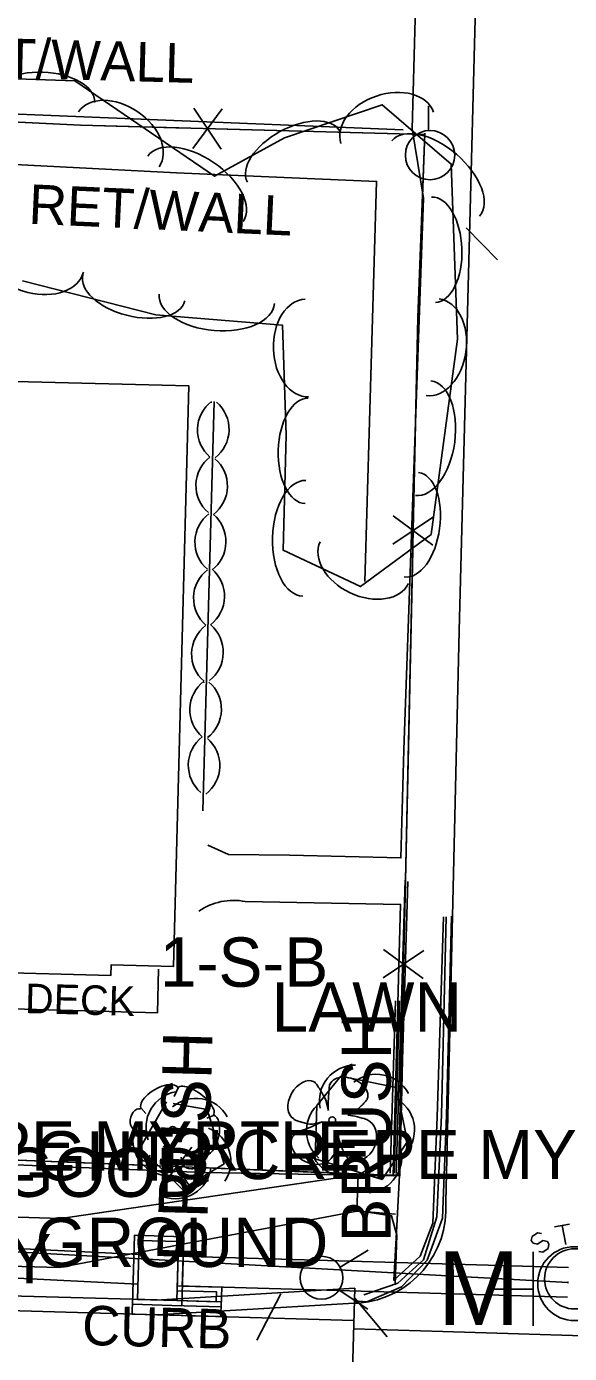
# Model space of a CAD drawing. Extents: x 978516 to 993312, y 1836504 to 1846212.
# Drawn here: x 992666.6 to 992721.7, y 1842882.7 to 1843017.4 of the extents above; entities that cross this region are included whole.
import ezdxf

# ---------------------------------------------------------------- set-up
doc = ezdxf.new("R2010")
doc.units = 0
for name, color, linetype in [('R_Drainage', 7, 'Continuous'), ('R_Proposed Road', 7, 'Continuous'), ('S_BUILDING', 7, 'Continuous'), ('S_CURB', 7, 'Continuous'), ('S_CURB_ANNOT', 7, 'Continuous'), ('S_EDGE_PAVEMENT', 7, 'Continuous'), ('S_FENCE', 7, 'Continuous'), ('S_FENCE_ANNOT', 7, 'Continuous'), ('S_IRON_PIN_ANNOT', 7, 'Continuous'), ('S_LANDSCAPING', 7, 'Continuous'), ('S_MANHOLE', 7, 'Continuous'), ('S_MISC_STRUCTURES', 7, 'Continuous'), ('S_MISC_STRUCTURES_ANNOT', 7, 'Continuous'), ('S_SIDEWALK', 7, 'Continuous'), ('S_STORM_SEWER', 7, 'Continuous'), ('S_STORM_SEWER_ANNOT', 7, 'Continuous'), ('S_SURVEY_TEXT_ANNOT', 7, 'Continuous'), ('S_TREE', 7, 'Continuous'), ('S_TREE_ANNOT', 7, 'Continuous'), ('S_UTILITY_POLE', 7, 'Continuous'), ('S_UTL_PT_SYM', 7, 'Continuous'), ('S_WALL', 7, 'Continuous'), ('S_WATER_UTILITIES', 7, 'Continuous')]:
    doc.layers.add(name, color=color, linetype=linetype)

msp = doc.modelspace()

# ---------------------------------------------------------------- linework, layer by layer
at = {"layer": 'R_Drainage'}
for p, q in [((992677.99, 1842892.77), (992612.06, 1842896.1)), ((992677.9, 1842889.77), (992611.98, 1842893.1)), ((992721.57, 1842891.46), (992681.98, 1842892.61)), ((992721.48, 1842888.46), (992681.9, 1842889.61))]:
    msp.add_line(p, q, dxfattribs=at)
for points in [[(992682.4, 1842889.59), (992682.54, 1842894.59), (992677.54, 1842894.73), (992677.34, 1842887.74), (992682.34, 1842887.59)], [(992681.88, 1842889.11), (992682.03, 1842894.11), (992678.03, 1842894.22), (992677.86, 1842888.22), (992681.85, 1842888.11)], [(992681.34, 1842887.62), (992686.34, 1842887.48), (992686.4, 1842889.48), (992682.4, 1842889.59)], [(992681.85, 1842888.11), (992685.85, 1842887.99), (992685.88, 1842888.99), (992681.88, 1842889.11)]]:
    msp.add_lwpolyline(points, dxfattribs=at)
for points in [[(992682.54, 1842894.59), (992677.54, 1842894.73), (992677.34, 1842887.74), (992682.34, 1842887.59)], [(992682.54, 1842894.59), (992677.54, 1842894.73), (992677.34, 1842887.74), (992682.34, 1842887.59)], [(992682.03, 1842894.11), (992678.03, 1842894.22), (992677.86, 1842888.22), (992681.85, 1842888.11)], [(992682.03, 1842894.11), (992678.03, 1842894.22), (992677.86, 1842888.22), (992681.85, 1842888.11)], [(992686.35, 1842887.98), (992677.36, 1842888.24), (992677.31, 1842886.74), (992686.31, 1842886.48)]]:
    msp.add_lwpolyline(points, close=True, dxfattribs=at)
at = {"layer": 'R_Proposed Road'}
for p, q in [((992700.23, 1842900.88), (992670.09, 1842896.45)), ((992700.12, 1842897.19), (992700.23, 1842900.88)), ((992528.4, 1842900.48), (992670.09, 1842896.45)), ((992669.94, 1842891.45), (992700.12, 1842897.19)), ((992528.26, 1842895.48), (992669.94, 1842891.45)), ((992528.17, 1842892.48), (992679.86, 1842888.17)), ((992528.13, 1842890.98), (992699.8, 1842886.1)), ((992679.72, 1842888.16), (992699.9, 1842889.37)), ((992698.6, 1842843.61), (992699.9, 1842889.37)), ((992679.81, 1842886.67), (992699.85, 1842887.86))]:
    msp.add_line(p, q, dxfattribs=at)
at = {"layer": 'S_BUILDING'}
msp.add_lwpolyline([(992683.07, 1842980.89), (992681.51, 1842922.01), (992675.19, 1842922.18), (992675.16, 1842921.1), (992662.51, 1842921.43), (992662.39, 1842916.58), (992652.58, 1842916.84), (992652.74, 1842922.87), (992643.89, 1842923.11), (992644.52, 1842947.03), (992645.96, 1842946.99), (992646.72, 1842976.01), (992665.28, 1842975.52), (992665.44, 1842981.36)], close=True, dxfattribs=at)
at = {"layer": 'S_CURB'}
for points in [[(992711.2, 1842996.95), (992714.38, 1842993.7)], [(992700.8, 1842888.71), (992704.25, 1842889.88), (992706.87, 1842892.25), (992708.23, 1842896.62), (992708.71, 1842906.93), (992709.18, 1842927.04)], [(992692.38, 1842888.79), (992689.96, 1842884.11)], [(992699.89, 1842888.37), (992703.18, 1842884.44)]]:
    msp.add_lwpolyline(points, dxfattribs=at)
at = {"layer": 'S_EDGE_PAVEMENT'}
for points in [[(992709.12, 1842898.12), (992710.47, 1842956.06), (992712.27, 1843024.64), (992713.71, 1843064.08), (992714.27, 1843106), (992714.63, 1843117.9)], [(992699.86, 1842888.09), (992701.13, 1842887.97), (992704.64, 1842889.5), (992707.25, 1842892.21), (992708.81, 1842896.48), (992709.19, 1842906.9), (992709.71, 1842927.11)], [(992699.85, 1842887.86), (992700.3, 1842887.86)], [(992699.78, 1842885.24), (992708.83, 1842884.96), (992724.19, 1842884.49), (992739.55, 1842884.02), (992754.91, 1842883.54), (992770.27, 1842883.07)]]:
    msp.add_lwpolyline(points, dxfattribs=at)
msp.add_arc((992699.52, 1842897.45), 9.63, 274.6679, 4.0148, dxfattribs=at)
at = {"layer": 'S_FENCE'}
for p, q in [((992686.44, 1843009), (992683.47, 1843004.98)), ((992686.33, 1843004.91), (992683.58, 1843009.08)), ((992703.74, 1842964.85), (992707.89, 1842967.62)), ((992707.83, 1842964.75), (992703.8, 1842967.71)), ((992702.76, 1842920.86), (992706.91, 1842923.63)), ((992706.85, 1842920.77), (992702.82, 1842923.73)), ((992703.9, 1842901.02), (992704.42, 1842918.51)), ((992680.33, 1842899.72), (992683.36, 1842903.69)), ((992680.5, 1842903.81), (992683.19, 1842899.6))]:
    msp.add_line(p, q, dxfattribs=at)
for points in [[(992706.95, 1843006.4), (992672.06, 1843007.34), (992627.2, 1843009.5)], [(992682.95, 1843007.05), (992672.06, 1843007.34), (992662.97, 1843007.78)], [(992706.95, 1843006.4), (992686.95, 1843006.94)], [(992659.9, 1842902.59), (992704.33, 1842900.79), (992704.96, 1842927.73), (992706.3, 1842987.83), (992707.01, 1843006.53)], [(992706.31, 1842988.22), (992707.01, 1843006.53)], [(992705.86, 1842968.23), (992706.3, 1842987.83), (992706.31, 1842988.22)], [(992705.33, 1842944.24), (992705.77, 1842964.23)], [(992704.88, 1842924.25), (992704.96, 1842927.73), (992705.33, 1842944.24)], [(992703.79, 1842900.81), (992704.33, 1842900.79), (992704.79, 1842920.25)], [(992659.9, 1842902.59), (992679.85, 1842901.78)], [(992683.84, 1842901.62), (992703.79, 1842900.81)]]:
    msp.add_lwpolyline(points, dxfattribs=at)
at = {"layer": 'S_IRON_PIN_ANNOT'}
for points in [[(992704.81, 1843006.89), (992628.4, 1843009.97)], [(992700.9, 1842961.06), (992702.11, 1843001.65), (992681.8, 1843002.52), (992646.39, 1843004.35)]]:
    msp.add_lwpolyline(points, dxfattribs=at)
at = {"layer": 'S_MANHOLE'}
for p, q in [((992718, 1842885.56), (992718, 1842893.06)), ((992713.82, 1842889.27), (992718, 1842889.27))]:
    msp.add_line(p, q, dxfattribs=at)
msp.add_circle((992722.2, 1842889.83), 3.75, dxfattribs=at)
at = {"layer": 'S_MISC_STRUCTURES'}
msp.add_lwpolyline([(992663.94, 1842917.73), (992679.87, 1842917.3), (992679.99, 1842921.72)], dxfattribs=at)
at = {"layer": 'S_SIDEWALK'}
for points in [[(992707.51, 1843068.23), (992706.33, 1843029.32), (992705.73, 1843006.96), (992706.86, 1842999.95), (992704.86, 1842943.99), (992704.57, 1842933.01), (992693.28, 1842933.3), (992687.09, 1842933.35), (992684.99, 1842934.32)], [(992705.28, 1842930.63), (992704.75, 1842912.53), (992704.45, 1842900.78)], [(992688.79, 1842928.6), (992704.55, 1842928.3), (992703.8, 1842900.76), (992684.53, 1842901.1), (992659.69, 1842902.11), (992659.96, 1842912.07), (992661.26, 1842914.65)], [(992708.89, 1842927.03), (992708.24, 1842906.75), (992707.81, 1842895.96), (992706.54, 1842892.61), (992703.87, 1842890.18), (992704.17, 1842895.71), (992704.43, 1842900.84), (992700.68, 1842900.87), (992700.23, 1842900.88)], [(992700.05, 1842897.17), (992700.75, 1842897.15), (992703.63, 1842896.72), (992704.15, 1842894.73), (992704.01, 1842889.7)], [(992700.12, 1842897.19), (992700.32, 1842897.17), (992704.02, 1842896.89)]]:
    msp.add_lwpolyline(points, dxfattribs=at)
msp.add_arc((992687.59, 1842922.58), 6.13, 78.7703, 124.8964, dxfattribs=at)
at = {"layer": 'S_STORM_SEWER'}
for p, q in [((992721.52, 1842889.96), (992602.49, 1842896.52)), ((992720.16, 1842895.58), (992721.67, 1842895.85)), ((992720.94, 1842895.74), (992721.29, 1842893.8)), ((992717.88, 1842894.61), (992717.8, 1842894.22)), ((992717.8, 1842894.22), (992717.99, 1842893.95)), ((992718.42, 1842895), (992717.88, 1842894.61)), ((992717.99, 1842893.95), (992718.42, 1842893.84)), ((992718.84, 1842894.92), (992718.42, 1842895)), ((992718.42, 1842893.84), (992718.96, 1842894.19)), ((992718.96, 1842894.19), (992719.43, 1842894.11)), ((992719.43, 1842894.11), (992719.58, 1842893.84)), ((992719.58, 1842893.84), (992719.5, 1842893.41)), ((992718.96, 1842893.02), (992718.57, 1842893.1)), ((992719.5, 1842893.41), (992718.96, 1842893.02))]:
    msp.add_line(p, q, dxfattribs=at)
msp.add_circle((992722.2, 1842890.31), 3.05, dxfattribs=at)
at = {"layer": 'S_TREE'}
for p, q in [((992681.98, 1842909.68), (992681.59, 1842908.82)), ((992678.18, 1842907.66), (992678.69, 1842907.08)), ((992697.24, 1842907.39), (992697, 1842908.29)), ((992685.55, 1842906.89), (992684.89, 1842906.61)), ((992696.6, 1842906.23), (992695.62, 1842906.01)), ((992699.19, 1842906.93), (992699.57, 1842907.1)), ((992677.52, 1842905.34), (992678.65, 1842905.34)), ((992698.13, 1842905.3), (992698.21, 1842904.86)), ((992678.69, 1842902.16), (992679.15, 1842902.86)), ((992682.37, 1842901.89), (992682.29, 1842902.66)), ((992684.77, 1842902.78), (992684.31, 1842903.2))]:
    msp.add_line(p, q, dxfattribs=at)
for points in [[(992649.71, 1843012.6), (992671.5, 1843011.85), (992685.67, 1843002.16), (992692.78, 1843006.07), (992702.66, 1843009.42), (992709.69, 1843003.4), (992710.33, 1842985.65), (992707.65, 1842965.84), (992700.46, 1842960.54), (992692.63, 1842964.23), (992692.95, 1842975.94), (992692.57, 1842987.05), (992679.7, 1842988.11), (992666.2, 1842991.56)], [(992685.62, 1842979.32), (992684.49, 1842937.78)], [(992685.34, 1842979.27), (992685.33, 1842979.17)], [(992684.57, 1842950.88), (992684.56, 1842950.78)], [(992695.89, 1842902.57), (992696.04, 1842907.89), (992698.49, 1842910.89), (992704.08, 1842909.74), (992705.25, 1842904.25), (992702.66, 1842900.39), (992695.43, 1842902.62)], [(992681.47, 1842908.11), (992684.92, 1842907.49), (992686.63, 1842901.97), (992682.4, 1842899.4), (992678.11, 1842903.62), (992680.81, 1842908.27)]]:
    msp.add_lwpolyline(points, dxfattribs=at)
for centre in [(992697.61, 1842906.41), (992681.42, 1842905.43)]:
    msp.add_circle(centre, 0.341, dxfattribs=at)
for centre, start, end in [((992687.58, 1842976.44), 127.647, 229.2439), ((992683.5, 1842976.49), 307.647, 49.2439), ((992687.42, 1842970.8), 127.647, 229.2439), ((992683.34, 1842970.75), 307.647, 49.2439), ((992687.32, 1842965.05), 127.647, 229.2439), ((992683.19, 1842965.11), 307.647, 49.2439), ((992687.18, 1842959.37), 127.647, 229.2439), ((992683.04, 1842959.55), 307.647, 49.2439), ((992686.98, 1842953.7), 127.647, 229.2439), ((992682.92, 1842953.89), 307.647, 49.2439), ((992686.8, 1842948.06), 127.647, 229.2439), ((992682.73, 1842948.1), 307.647, 49.2439), ((992686.65, 1842942.41), 127.647, 229.2439), ((992682.57, 1842942.37), 307.647, 49.2439), ((992699.95, 1842908.36), 89.9439, 191.5408), ((992702.11, 1842907.43), 27.5135, 129.1104), ((992682.36, 1842905.7), 99.0647, 200.6617), ((992683.78, 1842904.99), 29.076, 130.6729), ((992702.32, 1842905.43), 321.2515, 62.8484), ((992698.63, 1842905.32), 127.647, 229.2439), ((992681.02, 1842904.43), 174.7143, 276.3112), ((992683.69, 1842902.24), 326.4203, 68.0172), ((992701.02, 1842902.67), 275.2621, 16.859), ((992698.98, 1842904.31), 202.0556, 303.6525), ((992681.7, 1842902.08), 250.538, 352.1349)]:
    msp.add_arc(centre, 3.64, start, end, dxfattribs=at)
for centre, major_axis, ratio, start_param, end_param in [((992668.16, 1843009.84), (-5.34, 0.18), 0.540699, 3.141593, 6.283185), ((992703.18, 1843007.09), (-4.69, -1.59), 0.685311, 3.141593, 6.283185), ((992675.96, 1843005.91), (-4.09, 2.8), 0.685311, 3.141593, 6.283185), ((992693.69, 1843004.16), (-4.68, -2.58), 0.540699, 3.141593, 6.283185), ((992708.11, 1843001.95), (-4.45, 3.82), 0.55008, 3.141593, 6.283185), ((992683.75, 1843000.9), (-4.84, 3.31), 0.55008, 3.141593, 6.283185), ((992707.88, 1842994.71), (-0.19, 5.34), 0.540699, 3.141593, 6.283185), ((992667.57, 1842993.67), (4.8, -1.23), 0.685311, 3.141593, 6.283185), ((992677.49, 1842990.86), (5.18, -1.33), 0.540699, 3.141593, 6.283185), ((992685.9, 1842989.73), (5.85, -0.48), 0.55008, 3.141593, 6.283185), ((992695.03, 1842984.74), (0.17, -4.95), 0.685311, 3.141593, 6.283185), ((992707.81, 1842984.82), (0.66, 4.91), 0.685311, 3.141593, 6.283185), ((992706.83, 1842975.61), (0.79, 5.82), 0.55008, 3.141593, 6.283185), ((992695.02, 1842974.3), (-0.15, -5.34), 0.540699, 3.141593, 6.283185), ((992705.64, 1842966.82), (0.72, 5.3), 0.540699, 3.141593, 6.283185), ((992694.78, 1842965.44), (-0.16, -5.87), 0.55008, 3.141593, 6.283185), ((992700.87, 1842962.98), (4.48, -2.11), 0.685311, 3.141593, 6.283185), ((992680.09, 1842908.63), (1.86, 1.08), 0.471018, 0, 3.141593), ((992683.74, 1842908.31), (-1.81, 1.36), 0.405113, 3.141593, 6.283186), ((992694.73, 1842908.43), (-1.03, -1.88), 0.662338, 3.141593, 6.283185), ((992696.38, 1842909.3), (0.62, -1.01), 0.083512, 0, 3.141593), ((992697.31, 1842908.72), (-0.07, -1.33), 0.068203, 3.141593, 6.283185), ((992699.27, 1842909.3), (1.89, -0.74), 0.673998, 0, 3.141593), ((992677.85, 1842906.52), (0.31, 1.03), 0.646762, 0, 3.141593), ((992700.37, 1842907.83), (-0.798, -0.73), 0.092159, 0, 3.141593), ((992685.1, 1842904.9), (0.46, 2.04), 0.482994, 3.141593, 6.283185), ((992694.66, 1842906.28), (0.964, -0.267), 0.113563, 3.141593, 6.283185), ((992695.56, 1842905.79), (1.04, 0.44), 0.002756, 3.141593, 6.283185), ((992700.15, 1842906.7), (0.96, -0.23), 0.056001, 0, 3.141593), ((992700.23, 1842904.43), (0.88, 2.05), 0.81717, 3.141593, 6.283185), ((992678.16, 1842903.87), (-0.61, 1.6), 0.420543, 6.283185, 9.424777), ((992695.63, 1842903.75), (2.07, -0.93), 0.760068, 3.141593, 6.283185), ((992694.04, 1842905.02), (0.477, 0.328), 0.136309, 0, 3.141593), ((992697.89, 1842904.13), (0.19, 1.31), 0.114148, 3.141593, 5.822668), ((992698.46, 1842904.09), (0.254, -0.771), 0.051603, 3.141593, 6.283185), ((992699.04, 1842902.85), (-0.321, 0.467), 0.094289, 0, 3.141593), ((992680.62, 1842902.09), (-1.83, 0.19), 0.529943, 0, 3.141593), ((992683.58, 1842902.38), (1.09, 0.46), 0.711534, 3.141592, 6.283185)]:
    msp.add_ellipse(centre, major_axis=major_axis, ratio=ratio, start_param=start_param, end_param=end_param, dxfattribs=at)
at = {"layer": 'S_UTILITY_POLE'}
msp.add_line((992707.39, 1843006.83), (992707.39, 1843009.31), dxfattribs=at)
msp.add_circle((992707.53, 1843004.31), 2.5, dxfattribs=at)
at = {"layer": 'S_UTL_PT_SYM'}
msp.add_lwpolyline([(992721.52, 1842889.96), (992721.52, 1842890.01), (992721.52, 1842889.96), (992721.47, 1842889.96), (992721.52, 1842889.96), (992721.52, 1842889.91), (992721.52, 1842889.96), (992721.57, 1842889.96)], dxfattribs=at)
at = {"layer": 'S_WALL'}
for points in [[(992704.1, 1842901.01), (992704.62, 1842918.5), (992705, 1842930.75)], [(992703.5, 1842901.03), (992704.02, 1842918.52)]]:
    msp.add_lwpolyline(points, dxfattribs=at)
at = {"layer": 'S_WATER_UTILITIES'}
for p, q in [((992698.43, 1842891.49), (992701.25, 1842893.22)), ((992698.3, 1842889.18), (992701.21, 1842887.25))]:
    msp.add_line(p, q, dxfattribs=at)
msp.add_circle((992696.52, 1842890.43), 2.18, dxfattribs=at)

# ---------------------------------------------------------------- texts
at = {"layer": 'S_CURB_ANNOT'}
msp.add_text('CURB', height=4, rotation=358.4454, dxfattribs=at).set_placement((992672.19, 1842883.62))
at = {"layer": 'S_FENCE_ANNOT'}
msp.add_text('4" CHN LNK GOOD', height=5, dxfattribs=at).set_placement((992625, 1842898.63))
at = {"layer": 'S_LANDSCAPING'}
for rotation, p in [(358.4454, (992656.83, 1843012.36)), (357.3873, (992666.76, 1842997.36))]:
    msp.add_text('RET/WALL', height=4, rotation=rotation, dxfattribs=at).set_placement(p)
at = {"layer": 'S_MANHOLE'}
msp.add_text('M', height=7.46, dxfattribs=at).set_placement((992708.31, 1842885.65))
at = {"layer": 'S_MISC_STRUCTURES_ANNOT'}
msp.add_text('DECK', height=3, rotation=358.4454, dxfattribs=at).set_placement((992666.42, 1842917.28))
msp.add_text('GA LGHT', height=5, dxfattribs=at).set_placement((992652.23, 1842900.29))
at = {"layer": 'S_STORM_SEWER_ANNOT'}
for s, p in [('CONNECTS UNDER GROUND', (992602.49, 1842891.52)), ('DIR ONLY', (992637.55, 1842889.86))]:
    msp.add_text(s, height=5, dxfattribs=at).set_placement(p)
at = {"layer": 'S_SURVEY_TEXT_ANNOT'}
for s, p in [('1-S-B', (992680.12, 1842919.95)), ('LAWN', (992691.46, 1842915.38))]:
    msp.add_text(s, height=5, dxfattribs=at).set_placement(p)
at = {"layer": 'S_TREE_ANNOT'}
for rotation, p in [(89.9853, (992703.55, 1842894)), (88.4454, (992684.84, 1842891.95))]:
    msp.add_text('BRUSH', height=5, rotation=rotation, dxfattribs=at).set_placement(p)
for s, p in [('3" CREPE MYRTLE', (992640.53, 1842901.3)), ('3"CREPE MYRTLE', (992681.42, 1842900.43))]:
    msp.add_text(s, height=5, dxfattribs=at).set_placement(p)

doc.saveas('drawing.dxf')
